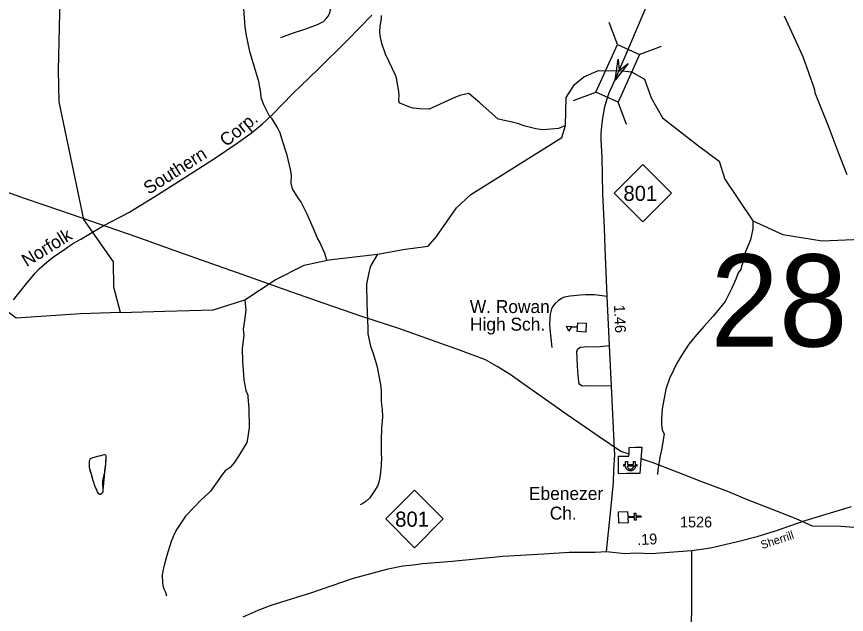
# Model space of a CAD drawing. Extents: x 1473865 to 1648260, y 639067 to 773536.
# Drawn here: x 1505606 to 1515215, y 710204 to 717123 of the extents above; entities that cross this region are included whole.
import ezdxf

# ---------------------------------------------------------------- set-up
doc = ezdxf.new("R2010")
doc.units = 0
for name, color, linetype in [('Exist Cultural Church CELL', 7, 'Continuous'), ('Exist Cultural Church Label', 7, 'Continuous'), ('Exist Cultural Educational Facility High CELL', 7, 'Continuous'), ('Exist Cultural Educational Facility High Label', 7, 'Continuous'), ('Exist Hydrographic Creek Single Shore', 7, 'Continuous'), ('Exist Hydrographic Misc Water Feature', 7, 'Continuous'), ('Exist Railroad Mainline', 7, 'Continuous'), ('Exist Railroad Mainline Label', 7, 'Continuous'), ('Exist Road Non-System Type 51', 7, 'Continuous'), ('Exist Road Primary NC Attributed', 7, 'Continuous'), ('Exist Road Primary NC Mileage Hundredths English Label', 7, 'Continuous'), ('Exist Road Primary NC Shield CELL', 7, 'Continuous'), ('Exist Road Primary NC Shield Number Label', 7, 'Continuous'), ('Exist Road Primary NC Structure Standard Bridge CELL', 7, 'Continuous'), ('Exist Road Secondary Mileage Hundredths English Label', 7, 'Continuous'), ('Exist Road Secondary Structure Standard Bridge Attributed CELL', 7, 'Continuous'), ('Exist Road Secondary Structure Standard Bridge Number Label', 7, 'Continuous'), ('Exist Road Secondary Type 51 Attributed', 7, 'Continuous'), ('Exist Road Secondary Type 51 Label', 7, 'Continuous'), ('Exist Road Secondary Type 51 Number Label', 7, 'Continuous'), ('Exist Utilities Electrical Power Substation CELL', 7, 'Continuous'), ('Exist Utilities Electrical Transmission Line', 7, 'Continuous')]:
    doc.layers.add(name, color=color, linetype=linetype)

msp = doc.modelspace()

# ---------------------------------------------------------------- linework, layer by layer
at = {"layer": 'Exist Cultural Church CELL'}
msp.add_lwpolyline([(1512681.3, 711395.7), (1512684.3, 711338.8), (1512760.3, 711342.5), (1512758.7, 711374.5), (1512774.7, 711375.3), (1512776.3, 711343.3), (1512836.3, 711346.3), (1512837.1, 711330.3), (1512777, 711327.3), (1512778.6, 711295.4), (1512762.7, 711294.6), (1512761.1, 711326.5), (1512685, 711322.8), (1512687.8, 711265.2), (1512581.4, 711260), (1512575, 711390.4)], close=True, dxfattribs=at)
at = {"layer": 'Exist Cultural Educational Facility High CELL'}
msp.add_lwpolyline([(1512196.7, 713472.4), (1512098.9, 713477.1), (1512101.1, 713523.1), (1512026.1, 713526.7), (1511999.6, 713480.8), (1511973.2, 713538.8), (1512101.6, 713532.7), (1512103.8, 713578.7), (1512201.6, 713574)], close=True, dxfattribs=at)
at = {"layer": 'Exist Hydrographic Creek Single Shore'}
for points in [[(1515223.3, 715290.3), (1515119.4, 715558.3), (1515013.5, 715834.8), (1514856.4, 716230), (1514843.5, 716287.7), (1514713.4, 716656.4), (1514496.3, 717126.9)], [(1506809.2, 713697.5), (1507323.6, 713714.9), (1507885.3, 713728.3), (1508249.8, 713846.6), (1508600.3, 714075), (1508936.2, 714245.4), (1509220.2, 714308.6), (1509785.8, 714375.2), (1510106.6, 714430.1), (1510372.6, 714465.8), (1510467.3, 714578.8), (1510698.3, 714909), (1510867.3, 715063.2), (1511917.8, 715725.7), (1511961.6, 715863), (1511970.3, 716186.5), (1512065.3, 716335.6), (1512175.4, 716425.3), (1512342.4, 716497.4), (1512459.3, 716495), (1512584, 716499.8), (1512727.4, 716485.6), (1512876.6, 716397.9), (1512952.9, 716183.4), (1513087.1, 715950.3), (1513503.4, 715627.1), (1513741.8, 715449), (1513809, 715241.6), (1514130.3, 714757.7), (1514478.4, 714602.9), (1514935.4, 714528), (1515386.4, 714545.3)], [(1506809.2, 713697.5), (1506346, 713681.7), (1505600.1, 713632.3), (1505293.5, 713864.9), (1505111.5, 713953.9), (1504945.3, 714005.4)]]:
    msp.add_lwpolyline(points, dxfattribs=at)
at = {"layer": 'Exist Hydrographic Misc Water Feature'}
for points in [[(1506809.2, 713697.5), (1506731.2, 713991.2), (1506727.2, 714283.4), (1506386.2, 714772.9), (1506100.3, 716137.6), (1506090.2, 716502.2), (1506115.2, 717496.3), (1506265.2, 718451.7), (1506315.3, 718933.3), (1506320.3, 719268), (1506235.3, 719627.5), (1506154.2, 719770.3), (1506083.3, 720021.2), (1506054.2, 720271.3), (1506093.3, 720615.2), (1506216.2, 720993.5), (1506221.3, 721252.7), (1506206.3, 721387.5), (1506226.3, 721544.8), (1506296.3, 721753.4), (1506553.2, 722148.7), (1506635.3, 722570.5), (1506826.3, 722986.8), (1506870.2, 723150.1)], [(1509199.6, 714303.1), (1509175.4, 714382.6), (1509117.7, 714511.6), (1509090.9, 714559.8), (1509040.6, 714676.9), (1508971.5, 714838.2), (1508896.1, 714983.5), (1508870.7, 715017.9), (1508802.7, 715128), (1508785.5, 715195.4), (1508787.6, 715289.3), (1508776.7, 715353.5), (1508739.6, 715518.1), (1508716.9, 715590.5), (1508675.3, 715723.2), (1508656.2, 715779.5), (1508629.2, 715832), (1508565.1, 715941.1), (1508531.8, 715979.7), (1508498.9, 716038.3), (1508470.1, 716102.8), (1508439.4, 716183.3), (1508433.7, 716241.2), (1508410.8, 716371.7), (1508346.7, 716588.8), (1508307, 716719.2), (1508264.6, 716924.1), (1508254.1, 717006.2), (1508237.8, 717214.4)], [(1511961.6, 715863), (1511879.4, 715827.3), (1511701.1, 715813.6), (1511618.9, 715824.5), (1511494.1, 715853.7), (1511407.4, 715887.5), (1511343.5, 715900.6), (1511257.5, 715921), (1511181.3, 715936.7), (1510970.1, 716123.3), (1510844, 716233.1), (1510750.8, 716213.9), (1510687.7, 716189.2), (1510383.3, 716052), (1510276.3, 716054.7), (1510196.9, 716065.2), (1510149.1, 716078.1), (1510034.7, 716125.1), (1510030.2, 716173.6), (1510037, 716196.7), (1510031.6, 716255.8), (1510018.4, 716340.4), (1510003.8, 716413.5), (1509992.4, 716445.7), (1509877, 716687.4), (1509834.9, 716812.5), (1509816.5, 716904.7), (1509813.3, 716944.8), (1509814.6, 717016.7), (1509832, 717096.3), (1509832.7, 717136.2)], [(1514130.3, 714757.7), (1514131.9, 714667.5), (1514105.6, 714540.2), (1514036.4, 714372.9), (1514029.8, 714314.5), (1514000.5, 714234.7), (1513991.7, 714194.9), (1513960.2, 714156.1), (1513934.9, 714084.7), (1513889.1, 713981.6), (1513810.3, 713827.2), (1513671.2, 713655.9), (1513565.1, 713538), (1513459, 713418.1), (1513391.4, 713332.9), (1513307, 713199.2), (1513249.2, 713102.4), (1513212, 713031.1), (1513166.3, 712936), (1513124, 712812.9), (1513079.9, 712581.9), (1513071.8, 712462.1), (1513073.1, 712422.1), (1513074.6, 712398.2), (1513079.6, 712342.1), (1513102.7, 712289.7), (1513075.5, 712110.3), (1513058.2, 712038.7), (1513031.3, 711879.3), (1513026.4, 711823.4)], [(1509785.8, 714375.2), (1509709, 714240.6), (1509696.4, 714208.9), (1509683.6, 714161.1), (1509658, 714024.5), (1509661.1, 713801.8), (1509672, 713513.8), (1509674.8, 713449.8), (1509704.4, 713309.4), (1509731, 713236.9), (1509776.3, 713084.2), (1509821.4, 712866.6), (1509827.1, 712791.4), (1509826.1, 712735.4), (1509829.1, 712679.4), (1509832.2, 712631.4), (1509835.7, 712599.4), (1509839.4, 712583.3), (1509841.7, 712487.3), (1509831.5, 712363.6), (1509828.7, 712211.8), (1509828, 712171.8), (1509825.8, 712043.9), (1509829.7, 712035.8), (1509827.6, 711924), (1509817.7, 711816.2), (1509804.4, 711748.5), (1509787.5, 711696.9), (1509744.3, 711621.8), (1509694.9, 711552.7), (1509648.2, 711509.7), (1509615.8, 711486.3), (1509583.5, 711470.9)], [(1508249.8, 713846.6), (1508262.2, 713726.3), (1508244.1, 713606.8), (1508230.6, 713503.6), (1508237.2, 713434.7), (1508219.5, 713277.5), (1508223, 713133.5), (1508237.1, 712917.4), (1508259, 712797.1), (1508282, 712742.7), (1508285.5, 712716.6), (1508295.3, 712588.5), (1508299.3, 712364.6), (1508280.9, 712237), (1508272.2, 712193.3), (1508177.3, 712035.2), (1508121.9, 711956.3), (1508079, 711905.1), (1508022.3, 711866.2), (1507977.3, 711811.1), (1507949.1, 711766.1), (1507852, 711631.6), (1507829.7, 711608), (1507740.2, 711527.8), (1507657.1, 711443.3), (1507563.5, 711340.2), (1507460.1, 711189.3), (1507435.3, 711141.8), (1507395.5, 711046.7), (1507346.2, 710884.3), (1507310.4, 710756.5), (1507301.8, 710724.6), (1507292.7, 710660.8), (1507294.9, 710564.9), (1507298.5, 710540.8), (1507311.7, 710500.6), (1507331.1, 710460.3), (1507340.3, 710420.1)], [(1506463.3, 712007.4), (1506480.5, 712015.6), (1506521.3, 712026.8), (1506561.5, 712039.5), (1506585.8, 712043.3), (1506605.9, 712049.9), (1506623.8, 712054.5), (1506634.4, 712051.5), (1506638.4, 712035.7), (1506638.5, 712007.2), (1506637.1, 711973.1), (1506636.5, 711942.5), (1506632.4, 711917.6), (1506629.1, 711894.9), (1506625.7, 711868.7), (1506622.3, 711843.8), (1506616.1, 711818.3), (1506612.8, 711794.2), (1506605.1, 711769.4), (1506601.8, 711748.8), (1506599.9, 711723.2), (1506601.6, 711700.4), (1506603.2, 711673.3), (1506602.8, 711652.7), (1506606, 711641.2), (1506605, 711623.4), (1506601.9, 711612.1), (1506593.1, 711601.6), (1506578.7, 711591.9), (1506568.7, 711592.1), (1506559, 711600.2), (1506543.7, 711624), (1506532.2, 711653.5), (1506513.1, 711693), (1506499.6, 711728.9), (1506489.6, 711760.5), (1506484.4, 711786.9), (1506471.6, 711822.8), (1506465.7, 711845), (1506459.7, 711869.3), (1506453.7, 711888), (1506451.2, 711906.5), (1506450.3, 711932.2), (1506450.5, 711974.2), (1506452.2, 711992.7), (1506463.3, 712007.4)], [(1506463.3, 712007.4), (1506480.5, 712015.6), (1506561.5, 712039.5), (1506623.8, 712054.5), (1506634.4, 712051.5), (1506638.4, 712035.7), (1506638.5, 712007.2), (1506636.5, 711942.5), (1506622.3, 711843.8), (1506606, 711641.2), (1506605, 711623.4), (1506601.9, 711612.1), (1506593.1, 711601.6), (1506578.7, 711591.9), (1506568.7, 711592.1), (1506559, 711600.2), (1506543.7, 711624), (1506513.1, 711693), (1506499.6, 711728.9), (1506489.6, 711760.5), (1506471.6, 711822.8), (1506453.7, 711888), (1506451.2, 711906.5), (1506450.3, 711932.2), (1506450.5, 711974.2), (1506452.2, 711992.7), (1506463.3, 712007.4)]]:
    msp.add_lwpolyline(points, dxfattribs=at)
at = {"layer": 'Exist Railroad Mainline'}
msp.add_lwpolyline([(1505570.5, 713844.4), (1505710.8, 714018.3), (1505820, 714152.4), (1505868.7, 714203.6), (1505926.9, 714254.3), (1505981.6, 714303.4), (1506060.2, 714361.2), (1506148.1, 714419.5), (1506196.6, 714452.7), (1506264.4, 714499.4), (1506350.2, 714546.7), (1506445, 714605.2), (1506609.9, 714702.5), (1506905, 714855.6), (1507238, 715060.8), (1507524.4, 715242.7), (1507895.7, 715479.3), (1508149.9, 715651.5), (1508321.7, 715773.1), (1508455.1, 715881.1), (1508562.6, 715981.6), (1508806, 716232), (1509093.8, 716511.7), (1509432.5, 716846.9), (1509720.5, 717138.6)], dxfattribs=at)
at = {"layer": 'Exist Road Non-System Type 51'}
for points in [[(1508667.2, 716880.3), (1508799.9, 716930.1), (1508954.8, 716981.4), (1509091.7, 717033), (1509160.2, 717067.9), (1509191.2, 717100.9), (1509216.9, 717132.3), (1509235.5, 717178.7), (1509242, 717212.6), (1509239.8, 717272.3), (1509176.9, 717652.4), (1509156.9, 717838.2), (1509129.2, 718098.2), (1508992.2, 718805), (1508867.5, 719616.9), (1508851.3, 719751.7)], [(1512445.3, 713884.5), (1512298.1, 713900.9), (1512194.1, 713903.6), (1512132, 713900.5), (1512015.9, 713888.2), (1511948.2, 713874.2), (1511915.9, 713858.8), (1511877.5, 713833.4), (1511841.1, 713801.9), (1511820.8, 713776.3), (1511801.8, 713739.2), (1511785, 713677.6), (1511780.3, 713625.6), (1511777.5, 713567.6), (1511778.8, 713509.6), (1511805.6, 713293.3)], [(1512494.7, 712844.2), (1512233.5, 712849.3), (1512155.4, 712846.4), (1512127.7, 712864.8), (1512121.9, 712874.9), (1512116.1, 712894.9), (1512105.7, 713013.1), (1512097.8, 713167.2), (1512095, 713247.3), (1512099.3, 713269.2), (1512103.5, 713279.1), (1512135.6, 713296.7), (1512219.8, 713303.4), (1512301.6, 713302.3), (1512361.7, 713305.3), (1512471.3, 713318.3)]]:
    msp.add_lwpolyline(points, dxfattribs=at)
at = {"layer": 'Exist Road Primary NC Attributed'}
for points in [[(1512584, 716499.8), (1512613.9, 716571.5), (1512664.8, 716688.8), (1512848.9, 717126.1), (1512923.3, 717293.1), (1513256.8, 718112), (1513329.2, 718281), (1513389.4, 718448.1)], [(1512437.8, 710932.4), (1512484, 711380.6), (1512516.8, 711730), (1512521, 711878), (1512531.6, 712053.6), (1512530.5, 712117.7), (1512494.7, 712844.2), (1512471.3, 713318.3), (1512445.3, 713884.5), (1512421.1, 714442.9), (1512414.4, 714675), (1512394.1, 715077.2), (1512386.1, 715491.2), (1512375, 715697.3), (1512375.9, 715773.1), (1512385.7, 715891), (1512392.5, 715946.9), (1512418.3, 716078.6), (1512441.4, 716158.2), (1512468.6, 716239.7), (1512584, 716499.8)], [(1508231.3, 710176), (1508404.4, 710253.6), (1508553.7, 710309.4), (1509014.9, 710455.4), (1509507.8, 710622.6), (1509908.5, 710730.3), (1510077.3, 710767.1), (1510196.9, 710776.4), (1510306.3, 710791.7), (1510648.3, 710820.6), (1511235.6, 710877.4), (1511711.1, 710905), (1512005.2, 710926.3), (1512305.9, 710926.3), (1512437.8, 710932.4)]]:
    msp.add_lwpolyline(points, dxfattribs=at)
at = {"layer": 'Exist Road Primary NC Shield CELL'}
for points in [[(1512524.2, 715080.1), (1512857.2, 715413.1), (1513190.2, 715080.1), (1512857.2, 714747.1)], [(1509880.9, 711308.6), (1510213.9, 711641.6), (1510546.9, 711308.6), (1510213.9, 710975.6)]]:
    msp.add_lwpolyline(points, close=True, dxfattribs=at)
at = {"layer": 'Exist Road Primary NC Structure Standard Bridge CELL'}
for p, q in [((1512564.6, 716798.4), (1512467.2, 717056.6)), ((1512816, 716684.6), (1513074.3, 716782)), ((1512056.1, 716150.8), (1512314.3, 716248.2)), ((1512668.9, 715873.6), (1512571.6, 716131.8))]:
    msp.add_line(p, q, dxfattribs=at)
msp.add_lwpolyline([(1512314.3, 716248.2), (1512563.4, 716798.9), (1512820.7, 716682.6), (1512571.6, 716131.8)], close=True, dxfattribs=at)
at = {"layer": 'Exist Road Secondary Structure Standard Bridge Attributed CELL'}
msp.add_lwpolyline([(1512687.1, 716579), (1512535.6, 716387.9), (1512571.2, 716629.1), (1512584, 716499.8)], close=True, dxfattribs=at)
at = {"layer": 'Exist Road Secondary Type 51 Attributed'}
for points in [[(1513425.6, 710945), (1513615.9, 710972.4), (1513676.1, 710983.4), (1513955, 711047.4), (1514179.6, 711104.1), (1514392.5, 711173), (1514736.1, 711290.2), (1515274.3, 711454.4)], [(1512437.8, 710932.4), (1512649.4, 710910.3), (1512777.6, 710916.5), (1512952.7, 710907.9), (1513425.6, 710945)], [(1513917.2, 706600.2), (1513837.9, 706757.2), (1513612.2, 707161.1), (1513592.7, 707197.5), (1513567.8, 707255), (1513552.2, 707302), (1513540.8, 707352.2), (1513531.8, 707410.2), (1513509.1, 707930.6), (1513494.6, 708184.6), (1513443.7, 708967.2), (1513428.2, 709149.4), (1513423.1, 709767.3), (1513421.7, 709975.5), (1513423.9, 710403.2), (1513425.6, 710945)]]:
    msp.add_lwpolyline(points, dxfattribs=at)
at = {"layer": 'Exist Utilities Electrical Power Substation CELL'}
msp.add_lwpolyline([(1512638.9, 711940), (1512658.5, 711940), (1512658.5, 711972.3), (1512678.3, 711972.3), (1512678.3, 711940), (1512749.1, 711940), (1512749.1, 711972.3), (1512768.9, 711972.3), (1512768.9, 711940), (1512788.5, 711940), (1512788.5, 711920.6), (1512768.9, 711920.6), (1512749.1, 711920.6), (1512678.3, 711920.6), (1512678.9, 711914.4), (1512680.2, 711909.1), (1512682.6, 711903.5), (1512686.3, 711898.1), (1512690.9, 711893.3), (1512693.5, 711891.3), (1512696.6, 711889.6), (1512700.4, 711887.5), (1512704.6, 711886.2), (1512709.3, 711885.3), (1512713, 711885), (1512717.2, 711885.1), (1512721.9, 711885.8), (1512726.2, 711887.1), (1512729.1, 711888.3), (1512732.5, 711890.1), (1512735.9, 711892.5), (1512739, 711895.3), (1512741.7, 711898.2), (1512743.8, 711901.1), (1512745.1, 711903.5), (1512746.6, 711906.2), (1512747.9, 711909.8), (1512748.4, 711912), (1512749.2, 711915.7), (1512749.4, 711918.6), (1512749.6, 711920.6), (1512771.2, 711920.6), (1512770.9, 711917.2), (1512770.5, 711914.5), (1512770, 711911.2), (1512769.2, 711907.8), (1512768.2, 711904.1), (1512767.1, 711901), (1512765.8, 711897.8), (1512764, 711894.3), (1512761.7, 711890.7), (1512759.2, 711887.1), (1512756.6, 711884), (1512753.9, 711881.3), (1512750.3, 711878.1), (1512746.5, 711875.2), (1512742.3, 711872.7), (1512737.9, 711870.4), (1512734.6, 711869), (1512731.4, 711868), (1512728.3, 711867.1), (1512724.5, 711866.3), (1512720.7, 711865.8), (1512717.3, 711865.5), (1512712.9, 711865.5), (1512709.9, 711865.7), (1512706.5, 711866.1), (1512702.9, 711866.8), (1512698.1, 711867.9), (1512693, 711869.8), (1512688.6, 711871.8), (1512685, 711873.9), (1512680.8, 711876.6), (1512677.7, 711879.3), (1512675.8, 711880.9), (1512673.4, 711883.3), (1512671.4, 711885.5), (1512668.7, 711888.8), (1512666, 711893.1), (1512664, 711896.8), (1512662.5, 711900.2), (1512661.3, 711903.3), (1512659.7, 711908.5), (1512658.9, 711912.9), (1512658.5, 711916.7), (1512658.2, 711920.6), (1512638.9, 711920.6)], close=True, dxfattribs=at)
at = {"layer": 'Exist Utilities Electrical Transmission Line'}
for points in [[(1512697.5, 712057.7), (1512601.1, 712090.3), (1512351, 712259.2), (1512188.4, 712371.1), (1511980, 712513.4), (1511769.9, 712663.9), (1511484.2, 712863.2), (1511319.4, 712979.2), (1511172.7, 713074.8), (1511037.6, 713152.4), (1510746.8, 713259.9), (1510464.1, 713359), (1510032, 713514), (1509605.6, 713653.1), (1509169.4, 713804.2), (1508729.2, 713957.3), (1508295.1, 714112.4), (1507864.9, 714261.3), (1507428.8, 714414.4), (1507000.8, 714571.3), (1506566.6, 714722.4), (1506130.3, 714869.4), (1505696.3, 715018.5), (1505266.2, 715171.4)], [(1512697.5, 712057.7), (1512698.3, 712085.1), (1512699.5, 712137.1), (1512772.2, 712139.8), (1512845.5, 712141.4), (1512838.5, 712041.6), (1512831.3, 711941.7), (1512822.1, 711835.9), (1512750.1, 711834.7), (1512674.2, 711833.4), (1512574.1, 711832.7), (1512575.3, 711942.7), (1512574.4, 712036.6), (1512639.3, 712036.3), (1512696.5, 712037.3), (1512697.5, 712057.7)], [(1517579.9, 711020.3), (1517220.1, 711060.5), (1516494.7, 711109), (1516109.3, 711147.4), (1515654, 711182.8), (1515150.5, 711220.6), (1514822.6, 711226.6), (1514631.6, 711310.7), (1514418.6, 711395.2), (1514050.3, 711537.5), (1513843.4, 711626), (1513540.7, 711737.3), (1513323.9, 711821.9), (1512975.5, 711958), (1512837.9, 712005.6)]]:
    msp.add_lwpolyline(points, dxfattribs=at)

# ---------------------------------------------------------------- texts
at = {"layer": 'Exist Cultural Church Label'}
for s, p in [('Ebenezer', (1511539.4, 711528.7)), ('Ch.', (1511780, 711301.3))]:
    msp.add_text(s, height=150, dxfattribs=at).set_placement(p)
at = {"layer": 'Exist Cultural Educational Facility High Label'}
for s, p in [('W. Rowan', (1510854.5, 713691.9)), ('High Sch.', (1510856.5, 713488.1))]:
    msp.add_text(s, height=150, dxfattribs=at).set_placement(p)
at = {"layer": 'Exist Railroad Mainline Label'}
for s, rotation, p in [('Corp.', 38.97365, (1508033.7, 715609.5)), ('Southern', 32.50508, (1507136.4, 715058.5)), ('Norfolk', 31.64816, (1505723.4, 714221.3))]:
    msp.add_text(s, height=150, rotation=rotation, dxfattribs=at).set_placement(p)
at = {"layer": 'Exist Road Primary NC Mileage Hundredths English Label'}
msp.add_text('1.46', height=125, rotation=272.6275, dxfattribs=at).set_placement((1512523, 713783.8))
at = {"layer": 'Exist Road Primary NC Shield Number Label'}
for p in [(1512633.3, 714990.4), (1509990, 711218.8)]:
    msp.add_text('801', height=175, dxfattribs=at).set_placement(p)
at = {"layer": 'Exist Road Secondary Mileage Hundredths English Label'}
msp.add_text('.19', height=125, rotation=2.77668, dxfattribs=at).set_placement((1512794.9, 711005.5))
at = {"layer": 'Exist Road Secondary Structure Standard Bridge Number Label'}
msp.add_text('28', height=1066.27, dxfattribs=at).set_placement((1513641.1, 713304.2))
at = {"layer": 'Exist Road Secondary Type 51 Label'}
msp.add_text('Sherrill', height=95, rotation=18.41166, dxfattribs=at).set_placement((1514240.6, 710959.1))
at = {"layer": 'Exist Road Secondary Type 51 Number Label'}
msp.add_text('1526', height=125, dxfattribs=at).set_placement((1513288, 711211))

doc.saveas('drawing.dxf')
